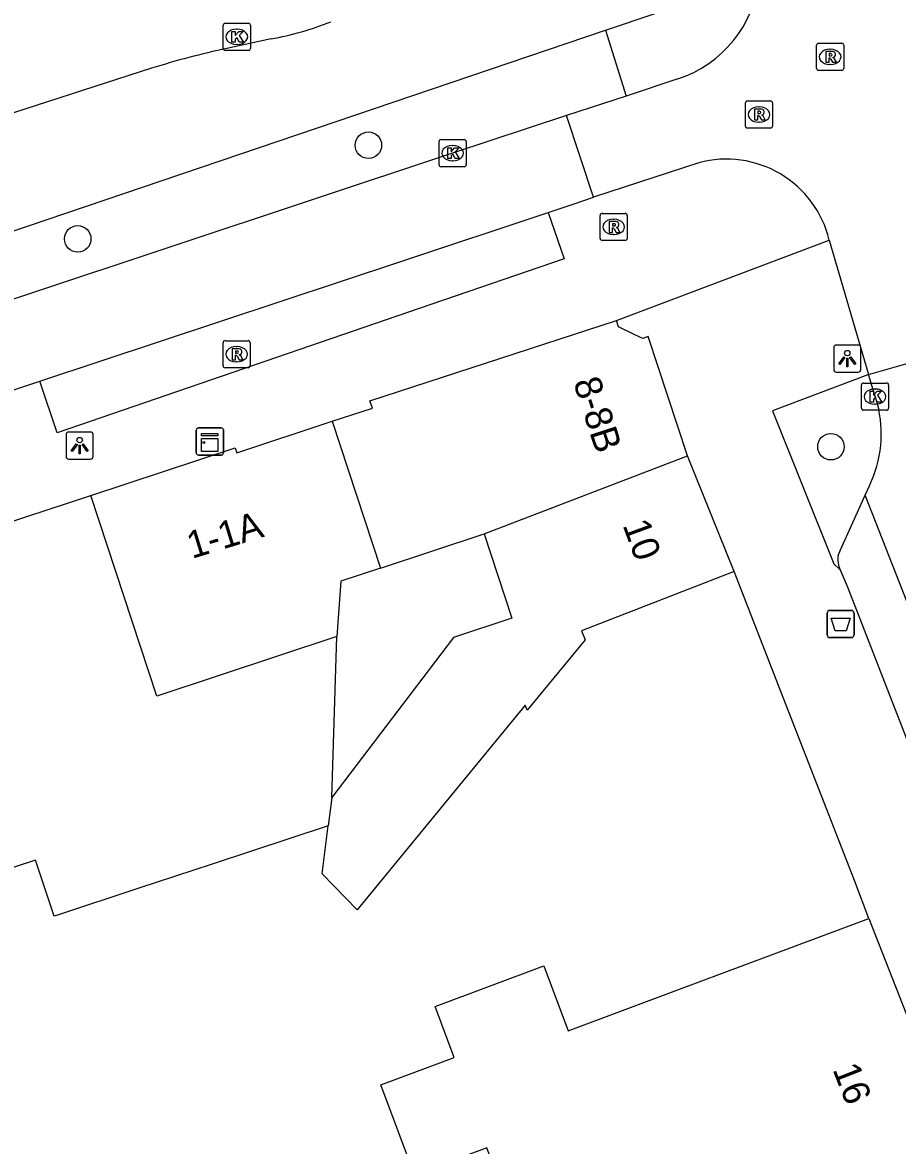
# Model space of a CAD drawing. Extents: x 161087 to 161922, y 382574 to 383873.
# Drawn here: x 161682.28 to 161714.55, y 382771.43 to 382812.8 of the extents above; entities that cross this region are included whole.
import ezdxf

# ---------------------------------------------------------------- set-up
doc = ezdxf.new("R2010")
doc.units = 0
for name, color, linetype in [('IMGEO_Afvalbak', 7, 'Continuous'), ('IMGEO_Boom', 7, 'Continuous'), ('IMGEO_Fietspad_gesloten', 7, 'Continuous'), ('IMGEO_Kast', 7, 'Continuous'), ('IMGEO_Kolk', 7, 'Continuous'), ('IMGEO_Lichtpunt', 7, 'Continuous'), ('IMGEO_Pand', 7, 'Continuous'), ('IMGEO_Pand_nummerreeks', 7, 'Continuous'), ('IMGEO_Parkeervlak_open', 7, 'Continuous'), ('IMGEO_Rijbaan_lokaal_gesloten', 7, 'Continuous'), ('IMGEO_Rijbaan_lokaal_open', 7, 'Continuous'), ('IMGEO_Rioolput', 7, 'Continuous'), ('IMGEO_Voetpad_open', 7, 'Continuous')]:
    doc.layers.add(name, color=color, linetype=linetype)

msp = doc.modelspace()

# ---------------------------------------------------------------- linework, layer by layer
at = {"layer": 'IMGEO_Afvalbak'}
for p, q in [((161711.954, 382790.239), (161711.954, 382791.039)), ((161711.954, 382791.039), (161711.954, 382790.239)), ((161712.054, 382791.139), (161712.844, 382791.139)), ((161712.844, 382791.139), (161712.054, 382791.139)), ((161712.944, 382791.039), (161712.944, 382790.239)), ((161712.944, 382790.239), (161712.944, 382791.039)), ((161712.844, 382790.139), (161712.054, 382790.139)), ((161712.054, 382790.139), (161712.844, 382790.139))]:
    msp.add_line(p, q, dxfattribs=at)
msp.add_lwpolyline([(161712.097, 382790.853), (161712.801, 382790.853), (161712.652, 382790.383), (161712.246, 382790.383), (161712.097, 382790.853)], dxfattribs=at)
for centre, start, end in [((161712.054, 382791.039), 90, 180), ((161712.054, 382791.039), 90, 180), ((161712.844, 382791.039), 0, 90), ((161712.844, 382791.039), 360, 90), ((161712.054, 382790.239), 180, 270), ((161712.054, 382790.239), 180, 270), ((161712.844, 382790.239), 270, 0), ((161712.844, 382790.239), 270, 0)]:
    msp.add_arc(centre, 0.1, start, end, dxfattribs=at)
at = {"layer": 'IMGEO_Boom'}
for centre in [(161695.036, 382808.277), (161684.319, 382804.826), (161712.092, 382797.171)]:
    msp.add_circle(centre, 0.489, dxfattribs=at)
at = {"layer": 'IMGEO_Fietspad_gesloten'}
for points in [[(161703.785, 382812.521), (161709.459, 382814.438)], [(161679.239, 382804.225), (161681.775, 382805.065), (161703.785, 382812.521)], [(161691.448, 382812.195), (161689.823, 382811.846)], [(161687.036, 382811.115), (161680.653, 382809.049), (161672.813, 382806.414), (161669.12, 382805.198)]]:
    msp.add_lwpolyline(points, dxfattribs=at)
for centre, radius, start, end in [((161689.445, 382823.344), 11.327, 280.1868, 291.8205), ((161696.331, 382781.355), 31.177, 102.0486, 107.3454)]:
    msp.add_arc(centre, radius, start, end, dxfattribs=at)
at = {"layer": 'IMGEO_Kast'}
for p, q in [((161688.768, 382797.864), (161689.609, 382797.864)), ((161689.609, 382797.864), (161688.768, 382797.864)), ((161688.693, 382796.939), (161688.693, 382797.78)), ((161688.693, 382797.78), (161688.693, 382796.939)), ((161689.693, 382797.789), (161689.693, 382796.948)), ((161689.693, 382796.948), (161689.693, 382797.789)), ((161689.618, 382796.864), (161688.777, 382796.864)), ((161688.777, 382796.864), (161689.618, 382796.864))]:
    msp.add_line(p, q, dxfattribs=at)
for points in [[(161688.888, 382797.654), (161689.488, 382797.654), (161689.488, 382797.569), (161688.888, 382797.569), (161688.888, 382797.654)], [(161688.888, 382797.479), (161689.488, 382797.479), (161689.488, 382796.99), (161688.888, 382796.99), (161688.888, 382797.479)]]:
    msp.add_lwpolyline(points, dxfattribs=at)
msp.add_circle((161688.972, 382797.328), 0.0377, dxfattribs=at)
for centre, start, end in [((161688.771, 382797.786), 92.4484, 184.2845), ((161688.771, 382797.786), 92.4484, 184.2845), ((161689.615, 382797.786), 2.4484, 94.2845), ((161689.615, 382797.786), 2.4484, 94.2845), ((161688.771, 382796.942), 182.4484, 274.2845), ((161688.771, 382796.942), 182.4484, 274.2845), ((161689.615, 382796.942), 272.4484, 4.2845), ((161689.615, 382796.942), 272.4484, 4.2845)]:
    msp.add_arc(centre, 0.0779, start, end, dxfattribs=at)
at = {"layer": 'IMGEO_Kolk'}
for p, q in [((161689.76, 382812.774), (161690.612, 382812.774)), ((161689.685, 382811.848), (161689.685, 382812.7)), ((161690.173, 382812.554), (161690.198, 382812.554)), ((161690.686, 382812.7), (161690.686, 382811.848)), ((161690.196, 382811.994), (161690.171, 382811.994)), ((161690.612, 382811.774), (161689.76, 382811.774)), ((161697.642, 382807.562), (161697.642, 382808.414)), ((161697.717, 382808.488), (161698.569, 382808.488)), ((161698.13, 382808.268), (161698.155, 382808.268)), ((161698.643, 382808.414), (161698.643, 382807.562)), ((161698.569, 382807.488), (161697.717, 382807.488)), ((161698.153, 382807.708), (161698.128, 382807.708)), ((161713.293, 382799.517), (161714.145, 382799.517)), ((161713.218, 382798.591), (161713.218, 382799.443)), ((161713.706, 382799.297), (161713.731, 382799.297)), ((161714.219, 382799.443), (161714.219, 382798.591)), ((161713.729, 382798.737), (161713.704, 382798.737)), ((161714.145, 382798.517), (161713.293, 382798.517))]:
    msp.add_line(p, q, dxfattribs=at)
for points in [[(161689.76, 382812.774), (161690.612, 382812.774)], [(161689.685, 382811.848), (161689.685, 382812.7)], [(161690.006, 382812.474), (161690.129, 382812.474), (161690.129, 382812.323), (161690.259, 382812.474), (161690.423, 382812.474), (161690.277, 382812.323), (161690.43, 382812.074), (161690.278, 382812.074), (161690.193, 382812.238), (161690.129, 382812.171), (161690.129, 382812.074), (161690.006, 382812.074), (161690.006, 382812.474)], [(161690.686, 382812.7), (161690.686, 382811.848)], [(161690.612, 382811.774), (161689.76, 382811.774)], [(161697.642, 382807.562), (161697.642, 382808.414)], [(161697.717, 382808.488), (161698.569, 382808.488)], [(161697.963, 382808.188), (161698.086, 382808.188), (161698.086, 382808.037), (161698.216, 382808.188), (161698.38, 382808.188), (161698.234, 382808.037), (161698.387, 382807.788), (161698.235, 382807.788), (161698.15, 382807.952), (161698.086, 382807.885), (161698.086, 382807.788), (161697.963, 382807.788), (161697.963, 382808.188)], [(161698.643, 382808.414), (161698.643, 382807.562)], [(161698.569, 382807.488), (161697.717, 382807.488)], [(161713.293, 382799.517), (161714.145, 382799.517)], [(161713.218, 382798.591), (161713.218, 382799.443)], [(161713.539, 382799.217), (161713.662, 382799.217), (161713.662, 382799.066), (161713.792, 382799.217), (161713.956, 382799.217), (161713.81, 382799.066), (161713.963, 382798.817), (161713.811, 382798.817), (161713.726, 382798.981), (161713.662, 382798.914), (161713.662, 382798.817), (161713.539, 382798.817), (161713.539, 382799.217)], [(161714.219, 382799.443), (161714.219, 382798.591)], [(161714.145, 382798.517), (161713.293, 382798.517)]]:
    msp.add_lwpolyline(points, dxfattribs=at)
for centre, start, end in [((161689.762, 382812.698), 91.552, 178.448), ((161689.762, 382812.698), 91.552, 178.448), ((161690.61, 382812.698), 1.552, 88.448), ((161690.61, 382812.698), 1.552, 88.448), ((161689.762, 382811.85), 181.552, 268.448), ((161689.762, 382811.85), 181.552, 268.448), ((161690.61, 382811.85), 271.552, 358.448), ((161690.61, 382811.85), 271.552, 358.448), ((161697.719, 382808.412), 91.552, 178.448), ((161697.719, 382808.412), 91.552, 178.448), ((161698.567, 382808.412), 1.552, 88.448), ((161698.567, 382808.412), 1.552, 88.448), ((161697.719, 382807.564), 181.552, 268.448), ((161697.719, 382807.564), 181.552, 268.448), ((161698.567, 382807.564), 271.552, 358.448), ((161698.567, 382807.564), 271.552, 358.448), ((161713.295, 382799.441), 91.552, 178.448), ((161713.295, 382799.441), 91.552, 178.448), ((161714.143, 382799.441), 1.552, 88.448), ((161714.143, 382799.441), 1.552, 88.448), ((161713.295, 382798.593), 181.552, 268.448), ((161713.295, 382798.593), 181.552, 268.448), ((161714.143, 382798.593), 271.552, 358.448), ((161714.143, 382798.593), 271.552, 358.448)]:
    msp.add_arc(centre, 0.0765, start, end, dxfattribs=at)
for centre, major_axis, ratio, start_param, end_param in [((161690.172, 382812.274), (-0.387, 0.002), 0.722429, 4.712389, 7.853982), ((161690.197, 382812.274), (-0.39, 0.002), 0.717154, 1.570796, 4.712389), ((161698.129, 382807.988), (-0.387, 0.002), 0.722429, 4.712389, 7.853982), ((161698.154, 382807.988), (-0.39, 0.002), 0.717154, 1.570796, 4.712389), ((161713.705, 382799.017), (-0.387, 0.002), 0.722429, 4.712389, 7.853982), ((161713.73, 382799.017), (-0.39, 0.002), 0.717154, 1.570796, 4.712389)]:
    msp.add_ellipse(centre, major_axis=major_axis, ratio=ratio, start_param=start_param, end_param=end_param, dxfattribs=at)
at = {"layer": 'IMGEO_Lichtpunt'}
for p, q in [((161712.196, 382800.821), (161712.196, 382800.014)), ((161712.196, 382800.821), (161712.196, 382800.014)), ((161713.098, 382800.916), (161712.29, 382800.916)), ((161713.098, 382800.916), (161712.29, 382800.916)), ((161713.192, 382800.014), (161713.192, 382800.821)), ((161713.192, 382800.014), (161713.192, 382800.821)), ((161712.29, 382799.92), (161713.098, 382799.92)), ((161712.29, 382799.92), (161713.098, 382799.92)), ((161683.893, 382797.617), (161683.893, 382796.81)), ((161683.893, 382797.617), (161683.893, 382796.81)), ((161684.795, 382797.712), (161683.987, 382797.712)), ((161684.795, 382797.712), (161683.987, 382797.712)), ((161684.889, 382796.81), (161684.889, 382797.617)), ((161684.889, 382796.81), (161684.889, 382797.617)), ((161683.987, 382796.716), (161684.795, 382796.716)), ((161683.987, 382796.716), (161684.795, 382796.716))]:
    msp.add_line(p, q, dxfattribs=at)
for points in [[(161712.57, 382800.485), (161712.609, 382800.457), (161712.421, 382800.195), (161712.383, 382800.222), (161712.57, 382800.485)], [(161712.672, 382800.437), (161712.719, 382800.437), (161712.719, 382800.115), (161712.672, 382800.115), (161712.672, 382800.437)], [(161712.782, 382800.457), (161712.82, 382800.484), (161713.007, 382800.222), (161712.968, 382800.194), (161712.782, 382800.457)], [(161684.267, 382797.281), (161684.306, 382797.253), (161684.118, 382796.991), (161684.08, 382797.018), (161684.267, 382797.281)], [(161684.369, 382797.233), (161684.416, 382797.233), (161684.416, 382796.911), (161684.369, 382796.911), (161684.369, 382797.233)], [(161684.479, 382797.253), (161684.517, 382797.28), (161684.704, 382797.018), (161684.665, 382796.99), (161684.479, 382797.253)]]:
    msp.add_lwpolyline(points, dxfattribs=at)
for centre in [(161712.695, 382800.619), (161684.392, 382797.415)]:
    msp.add_circle(centre, 0.0994, dxfattribs=at)
for centre, start, end in [((161712.29, 382800.821), 90, 180), ((161712.29, 382800.821), 90, 180), ((161713.098, 382800.821), 0, 90), ((161713.098, 382800.821), 0, 90), ((161712.29, 382800.014), 180, 270), ((161712.29, 382800.014), 180, 270), ((161713.098, 382800.014), 270, 0), ((161713.098, 382800.014), 270, 360), ((161683.987, 382797.617), 90, 180), ((161683.987, 382797.617), 90, 180), ((161684.795, 382797.617), 0, 90), ((161684.795, 382797.617), 0, 90), ((161683.987, 382796.81), 180, 270), ((161683.987, 382796.81), 180, 270), ((161684.795, 382796.81), 270, 0), ((161684.795, 382796.81), 270, 360)]:
    msp.add_arc(centre, 0.0946, start, end, dxfattribs=at)
at = {"layer": 'IMGEO_Pand'}
for points in [[(161693.704, 382798.107), (161695.185, 382798.594), (161695.096, 382798.864), (161704.19, 382801.815)], [(161706.798, 382796.831), (161705.351, 382801.228), (161705.151, 382801.16), (161704.84, 382801.309), (161704.256, 382801.587), (161704.19, 382801.815)], [(161684.809, 382795.379), (161690.126, 382797.128), (161690.185, 382796.95), (161693.704, 382798.107)], [(161693.704, 382798.107), (161695.483, 382792.7)], [(161699.308, 382793.957), (161706.798, 382796.831)], [(161708.527, 382792.577), (161706.798, 382796.831)], [(161673.242, 382791.575), (161679.143, 382793.516), (161684.809, 382795.379)], [(161693.88, 382790.184), (161687.242, 382787.983), (161684.809, 382795.379)], [(161699.308, 382793.957), (161700.33, 382790.85), (161698.177, 382790.142), (161693.691, 382784.249)], [(161695.483, 382792.7), (161699.308, 382793.957)], [(161708.527, 382792.577), (161702.9, 382790.39), (161703.029, 382790.057), (161700.892, 382787.466), (161700.822, 382787.646), (161694.622, 382780.114), (161693.332, 382781.441), (161693.557, 382783.201)], [(161695.483, 382792.7), (161694.02, 382792.219), (161693.88, 382790.184)], [(161693.557, 382783.201), (161689.279, 382781.794), (161686.574, 382780.904), (161683.613, 382779.93), (161683.448, 382779.876), (161682.763, 382781.94), (161681.287, 382781.455), (161677.03, 382780.056), (161674.804, 382786.826), (161673.242, 382791.575)], [(161693.691, 382784.249), (161693.88, 382790.184)], [(161693.691, 382784.249), (161693.557, 382783.201)], [(161717.442, 382769.706), (161717.151, 382769.589), (161712.462, 382767.846), (161707.286, 382765.805), (161707.01, 382766.461), (161705.007, 382765.888), (161703.635, 382769.562), (161700.503, 382768.392), (161699.402, 382771.342), (161696.738, 382770.348), (161695.501, 382773.661), (161698.195, 382774.667), (161697.494, 382776.547), (161701.509, 382778.046), (161702.403, 382775.651), (161706.409, 382777.146), (161708.984, 382778.107), (161713.487, 382779.788)], [(161713.487, 382779.788), (161717.442, 382769.706)]]:
    msp.add_lwpolyline(points, dxfattribs=at)
at = {"layer": 'IMGEO_Parkeervlak_open'}
msp.add_lwpolyline([(161712.358, 382793.159), (161712.447, 382793.368), (161713.35, 382795.381)], dxfattribs=at)
msp.add_arc((161713.188, 382793.012), 0.843, 169.9517, 206.5534, dxfattribs=at)
at = {"layer": 'IMGEO_Rijbaan_lokaal_gesloten'}
for points in [[(161702.348, 382809.37), (161698.143, 382807.988), (161682.511, 382802.794), (161679.974, 382801.957)], [(161703.341, 382806.363), (161702.348, 382809.37)], [(161701.663, 382805.805), (161702.586, 382806.112), (161703.341, 382806.363)], [(161682.921, 382799.59), (161696.266, 382804.008), (161701.663, 382805.805)], [(161618.873, 382778.339), (161619.539, 382778.558), (161637.495, 382784.499), (161640.402, 382785.458), (161656.819, 382790.909), (161682.921, 382799.59)]]:
    msp.add_lwpolyline(points, dxfattribs=at)
at = {"layer": 'IMGEO_Rijbaan_lokaal_open'}
for points in [[(161706.446, 382810.719), (161704.541, 382810.09)], [(161704.541, 382810.09), (161702.348, 382809.37)], [(161707.227, 382807.634), (161703.341, 382806.363)], [(161712.03, 382804.783), (161713.481, 382799.83)], [(161713.481, 382799.83), (161718.727, 382801.324)], [(161713.808, 382798.752), (161713.719, 382799.017), (161713.481, 382799.83)], [(161713.35, 382795.381), (161713.509, 382795.734)], [(161722.127, 382773.053), (161719.449, 382779.866), (161713.35, 382795.381)]]:
    msp.add_lwpolyline(points, dxfattribs=at)
for centre, radius, start, end in [((161705.072, 382814.912), 4.412, 288.141, 353.8327), ((161708.238, 382803.865), 3.902, 13.6014, 105.013), ((161709.559, 382797.649), 4.389, 334.1317, 14.5523)]:
    msp.add_arc(centre, radius, start, end, dxfattribs=at)
at = {"layer": 'IMGEO_Rioolput'}
for p, q in [((161711.562, 382811.107), (161711.562, 382811.959)), ((161711.637, 382812.033), (161712.489, 382812.033)), ((161712.563, 382811.959), (161712.563, 382811.107)), ((161712.05, 382811.813), (161712.075, 382811.813)), ((161712.073, 382811.253), (161712.048, 382811.253)), ((161712.489, 382811.033), (161711.637, 382811.033)), ((161709.013, 382809.909), (161709.865, 382809.909)), ((161708.938, 382808.983), (161708.938, 382809.835)), ((161709.426, 382809.689), (161709.451, 382809.689)), ((161709.939, 382809.835), (161709.939, 382808.983)), ((161709.449, 382809.129), (161709.424, 382809.129)), ((161709.865, 382808.909), (161709.013, 382808.909)), ((161703.655, 382805.769), (161704.507, 382805.769)), ((161703.58, 382804.843), (161703.58, 382805.695)), ((161704.068, 382805.549), (161704.093, 382805.549)), ((161704.581, 382805.695), (161704.581, 382804.843)), ((161704.091, 382804.989), (161704.066, 382804.989)), ((161704.507, 382804.769), (161703.655, 382804.769)), ((161689.677, 382800.152), (161689.677, 382801.004)), ((161689.752, 382801.078), (161690.604, 382801.078)), ((161690.165, 382800.858), (161690.19, 382800.858)), ((161690.678, 382801.004), (161690.678, 382800.152)), ((161690.604, 382800.078), (161689.752, 382800.078)), ((161690.188, 382800.298), (161690.163, 382800.298))]:
    msp.add_line(p, q, dxfattribs=at)
for points in [[(161711.562, 382811.107), (161711.562, 382811.959)], [(161711.637, 382812.033), (161712.489, 382812.033)], [(161712.563, 382811.959), (161712.563, 382811.107)], [(161712.151, 382811.731), (161711.899, 382811.733), (161711.899, 382811.333)], [(161712.077, 382811.652), (161712.023, 382811.652), (161712.023, 382811.571)], [(161712.023, 382811.571), (161712.075, 382811.571)], [(161711.899, 382811.333), (161712.023, 382811.333), (161712.023, 382811.495), (161712.034, 382811.495)], [(161712.081, 382811.466), (161712.152, 382811.333), (161712.292, 382811.333), (161712.227, 382811.459)], [(161712.489, 382811.033), (161711.637, 382811.033)], [(161709.013, 382809.909), (161709.865, 382809.909)], [(161708.938, 382808.983), (161708.938, 382809.835)], [(161709.527, 382809.607), (161709.275, 382809.609), (161709.275, 382809.209)], [(161709.453, 382809.528), (161709.399, 382809.528), (161709.399, 382809.447)], [(161709.399, 382809.447), (161709.451, 382809.447)], [(161709.939, 382809.835), (161709.939, 382808.983)], [(161709.275, 382809.209), (161709.399, 382809.209), (161709.399, 382809.371), (161709.41, 382809.371)], [(161709.457, 382809.342), (161709.528, 382809.209), (161709.668, 382809.209), (161709.603, 382809.335)], [(161709.865, 382808.909), (161709.013, 382808.909)], [(161703.655, 382805.769), (161704.507, 382805.769)], [(161703.58, 382804.843), (161703.58, 382805.695)], [(161704.169, 382805.467), (161703.917, 382805.469), (161703.917, 382805.069)], [(161704.095, 382805.388), (161704.041, 382805.388), (161704.041, 382805.307)], [(161704.041, 382805.307), (161704.093, 382805.307)], [(161704.581, 382805.695), (161704.581, 382804.843)], [(161703.917, 382805.069), (161704.041, 382805.069), (161704.041, 382805.231), (161704.052, 382805.231)], [(161704.099, 382805.202), (161704.17, 382805.069), (161704.31, 382805.069), (161704.245, 382805.195)], [(161704.507, 382804.769), (161703.655, 382804.769)], [(161689.677, 382800.152), (161689.677, 382801.004)], [(161689.752, 382801.078), (161690.604, 382801.078)], [(161690.266, 382800.776), (161690.014, 382800.778), (161690.014, 382800.378)], [(161690.678, 382801.004), (161690.678, 382800.152)], [(161690.014, 382800.378), (161690.138, 382800.378), (161690.138, 382800.54), (161690.149, 382800.54)], [(161690.192, 382800.697), (161690.138, 382800.697), (161690.138, 382800.616)], [(161690.138, 382800.616), (161690.19, 382800.616)], [(161690.196, 382800.511), (161690.267, 382800.378), (161690.407, 382800.378), (161690.342, 382800.504)], [(161690.604, 382800.078), (161689.752, 382800.078)]]:
    msp.add_lwpolyline(points, dxfattribs=at)
for centre, radius, start, end in [((161711.639, 382811.957), 0.0765, 91.552, 178.448), ((161711.639, 382811.957), 0.0765, 91.552, 178.448), ((161712.487, 382811.957), 0.0765, 1.552, 88.448), ((161712.487, 382811.957), 0.0765, 1.552, 88.448), ((161712.059, 382811.76), 0.19, 274.7715, 282.9687), ((161712.083, 382811.556), 0.0964, 77.0061, 93.1865), ((161712.097, 382811.613), 0.0378, 276.6634, 79.6772), ((161712.15, 382811.621), 0.109, 350.3612, 89.416), ((161712.148, 382811.621), 0.112, 277.5842, 350.9817), ((161712.132, 382811.406), 0.108, 29.5134, 73.7905), ((161711.639, 382811.109), 0.0765, 181.552, 268.448), ((161711.639, 382811.109), 0.0765, 181.552, 268.448), ((161712.033, 382811.442), 0.0533, 26.0293, 88.6989), ((161712.487, 382811.109), 0.0765, 271.552, 358.448), ((161712.487, 382811.109), 0.0765, 271.552, 358.448), ((161709.015, 382809.833), 0.0765, 91.552, 178.448), ((161709.015, 382809.833), 0.0765, 91.552, 178.448), ((161709.863, 382809.833), 0.0765, 1.552, 88.448), ((161709.863, 382809.833), 0.0765, 1.552, 88.448), ((161709.435, 382809.636), 0.19, 274.7715, 282.9687), ((161709.459, 382809.432), 0.0964, 77.0061, 93.1865), ((161709.473, 382809.489), 0.0378, 276.6634, 79.6772), ((161709.526, 382809.497), 0.109, 350.3612, 89.416), ((161709.524, 382809.497), 0.112, 277.5842, 350.9817), ((161709.409, 382809.318), 0.0533, 26.0293, 88.6989), ((161709.508, 382809.282), 0.108, 29.5134, 73.7905), ((161709.015, 382808.985), 0.0765, 181.552, 268.448), ((161709.015, 382808.985), 0.0765, 181.552, 268.448), ((161709.863, 382808.985), 0.0765, 271.552, 358.448), ((161709.863, 382808.985), 0.0765, 271.552, 358.448), ((161703.657, 382805.693), 0.0765, 91.552, 178.448), ((161703.657, 382805.693), 0.0765, 91.552, 178.448), ((161704.505, 382805.693), 0.0765, 1.552, 88.448), ((161704.505, 382805.693), 0.0765, 1.552, 88.448), ((161704.077, 382805.496), 0.19, 274.7715, 282.9687), ((161704.101, 382805.292), 0.0964, 77.0061, 93.1865), ((161704.115, 382805.349), 0.0378, 276.6634, 79.6772), ((161704.168, 382805.357), 0.109, 350.3612, 89.416), ((161704.166, 382805.357), 0.112, 277.5842, 350.9817), ((161704.051, 382805.178), 0.0533, 26.0293, 88.6989), ((161704.15, 382805.142), 0.108, 29.5134, 73.7905), ((161703.657, 382804.845), 0.0765, 181.552, 268.448), ((161703.657, 382804.845), 0.0765, 181.552, 268.448), ((161704.505, 382804.845), 0.0765, 271.552, 358.448), ((161704.505, 382804.845), 0.0765, 271.552, 358.448), ((161689.754, 382801.002), 0.0765, 91.552, 178.448), ((161689.754, 382801.002), 0.0765, 91.552, 178.448), ((161690.265, 382800.666), 0.109, 350.3612, 89.416), ((161690.602, 382801.002), 0.0765, 1.552, 88.448), ((161690.602, 382801.002), 0.0765, 1.552, 88.448), ((161690.148, 382800.487), 0.0533, 26.0293, 88.6989), ((161690.174, 382800.805), 0.19, 274.7715, 282.9687), ((161690.198, 382800.601), 0.0964, 77.0061, 93.1865), ((161690.212, 382800.658), 0.0378, 276.6634, 79.6772), ((161690.263, 382800.666), 0.112, 277.5842, 350.9817), ((161690.247, 382800.451), 0.108, 29.5134, 73.7905), ((161689.754, 382800.154), 0.0765, 181.552, 268.448), ((161689.754, 382800.154), 0.0765, 181.552, 268.448), ((161690.602, 382800.154), 0.0765, 271.552, 358.448), ((161690.602, 382800.154), 0.0765, 271.552, 358.448)]:
    msp.add_arc(centre, radius, start, end, dxfattribs=at)
for centre, major_axis, ratio, start_param, end_param in [((161712.049, 382811.533), (-0.387, 0.002), 0.722429, 4.712389, 7.853982), ((161712.074, 382811.533), (-0.39, 0.002), 0.717154, 1.570796, 4.712389), ((161709.425, 382809.409), (-0.387, 0.002), 0.722429, 4.712389, 7.853982), ((161709.45, 382809.409), (-0.39, 0.002), 0.717154, 1.570796, 4.712389), ((161704.067, 382805.269), (-0.387, 0.002), 0.722429, 4.712389, 7.853982), ((161704.092, 382805.269), (-0.39, 0.002), 0.717154, 1.570796, 4.712389), ((161690.164, 382800.578), (-0.387, 0.002), 0.722429, 4.712389, 7.853982), ((161690.189, 382800.578), (-0.39, 0.002), 0.717154, 1.570796, 4.712389)]:
    msp.add_ellipse(centre, major_axis=major_axis, ratio=ratio, start_param=start_param, end_param=end_param, dxfattribs=at)
at = {"layer": 'IMGEO_Voetpad_open'}
for points in [[(161703.785, 382812.521), (161704.541, 382810.09)], [(161701.663, 382805.805), (161702.253, 382804.092), (161696.911, 382802.26), (161683.568, 382797.683), (161682.921, 382799.59)], [(161704.19, 382801.815), (161712.03, 382804.783)], [(161713.481, 382799.83), (161713.454, 382799.822), (161709.938, 382798.495), (161712.195, 382792.853), (161712.434, 382792.635)], [(161713.487, 382779.788), (161712.955, 382781.187), (161710.53, 382787.424), (161708.527, 382792.577)], [(161712.434, 382792.635), (161712.687, 382792.031), (161715.664, 382784.389), (161720.09, 382773.118)]]:
    msp.add_lwpolyline(points, dxfattribs=at)

# ---------------------------------------------------------------- texts
at = {"layer": 'IMGEO_Pand_nummerreeks'}
for s, rotation, p in [('8-8B', 288.0086, (161702.583, 382799.553)), ('1-1A', 17.0568, (161688.532, 382793.036)), ('10', 290.2023, (161704.404, 382794.286)), ('16', 291.4192, (161712.143, 382774.234))]:
    msp.add_text(s, height=1, rotation=rotation, dxfattribs=at).set_placement(p)

doc.saveas('drawing.dxf')
